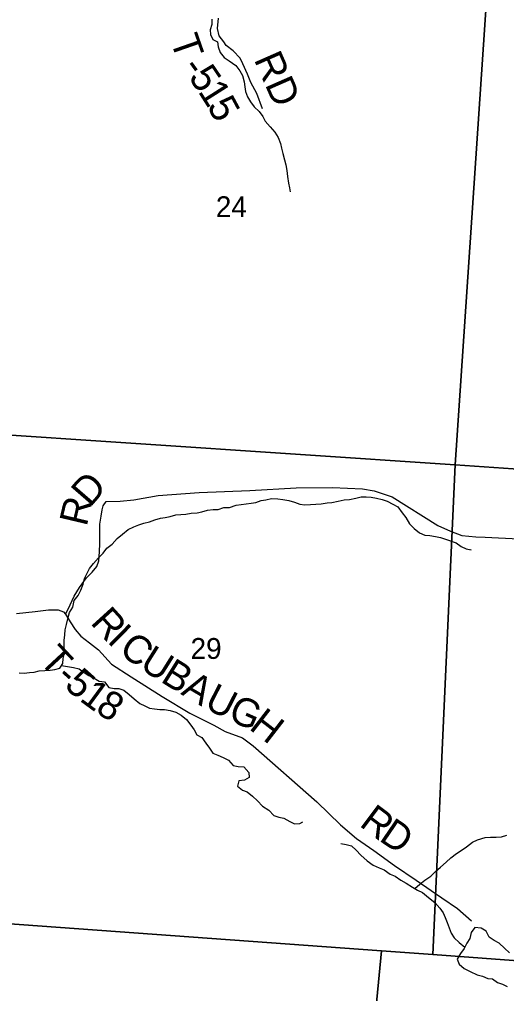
# Model space of a CAD drawing. Extents: x 1578669 to 1989827, y 208020 to 553079.
# Drawn here: x 1871261 to 1876425, y 410123 to 420455 of the extents above; entities that cross this region are included whole.
import ezdxf

# ---------------------------------------------------------------- set-up
doc = ezdxf.new("R2010")
doc.units = 0
for name, color, linetype in [('GM_X_County_Road', 7, 'Continuous'), ('GM_X_County_Road_Text', 7, 'Continuous'), ('GM_X_Minor_Lake', 7, 'Continuous'), ('GM_X_Minor_River', 7, 'Continuous'), ('GM_X_Section', 7, 'Continuous'), ('GM_X_Section_Text', 7, 'Continuous'), ('GM_X_Township_Road', 7, 'Continuous'), ('GM_X_Township_Road_Text', 7, 'Continuous')]:
    doc.layers.add(name, color=color, linetype=linetype)

msp = doc.modelspace()

# ---------------------------------------------------------------- linework, layer by layer
at = {"layer": 'GM_X_County_Road'}
for points in [[(1871750, 414147), (1871750, 414147), (1871776, 414199), (1871839, 414337), (1871896, 414431), (1871972, 414533), (1872032, 414592), (1872081, 414654), (1872101, 414714), (1872110, 414810), (1872112, 414897), (1872113, 414973), (1872113, 415101), (1872126, 415187), (1872136, 415255), (1872149, 415297), (1872181, 415343), (1872327, 415346), (1872473, 415359), (1872731, 415406), (1873165, 415438), (1873703, 415459), (1874196, 415488), (1874578, 415492), (1874897, 415476), (1875021, 415455), (1875211, 415392), (1875697, 415089), (1875829, 415028), (1875951, 414981), (1876098, 414966), (1876198, 414963), (1876554, 414947)], [(1871230, 414156), (1871426, 414177), (1871568, 414192), (1871670, 414192), (1871726, 414173), (1871750, 414147)]]:
    msp.add_lwpolyline(points, dxfattribs=at)
at = {"layer": 'GM_X_Minor_Lake'}
msp.add_lwpolyline([(1876457, 410555), (1876404, 410605), (1876347, 410656), (1876294, 410687), (1876241, 410720), (1876208, 410785), (1876155, 410816), (1876087, 410822), (1876050, 410769), (1876034, 410707), (1876005, 410656), (1875974, 410602), (1875935, 410547), (1875901, 410488), (1875924, 410433), (1875977, 410388), (1876038, 410356), (1876112, 410323), (1876171, 410307), (1876225, 410282), (1876277, 410279), (1876330, 410242), (1876381, 410221), (1876433, 410198)], dxfattribs=at)
at = {"layer": 'GM_X_Minor_River'}
for points in [[(1873299, 420459), (1873300, 420401), (1873283, 420347), (1873286, 420295), (1873311, 420244), (1873362, 420219), (1873369, 420165), (1873389, 420104), (1873430, 420053), (1873483, 420018), (1873556, 419966), (1873597, 419911), (1873624, 419861), (1873642, 419794), (1873651, 419740), (1873656, 419690), (1873677, 419635), (1873712, 419582), (1873750, 419529)], [(1873750, 419529), (1873801, 419480), (1873840, 419425), (1873865, 419375), (1873920, 419315), (1873968, 419260), (1874003, 419205), (1874028, 419141), (1874039, 419090), (1874053, 419032), (1874070, 418966), (1874085, 418913), (1874095, 418855), (1874104, 418791), (1874114, 418718), (1874125, 418668), (1874130, 418626)], [(1873768, 415331), (1873823, 415354), (1873873, 415361), (1873933, 415374), (1873999, 415372), (1874053, 415365), (1874115, 415354), (1874176, 415334), (1874232, 415315), (1874288, 415308), (1874348, 415310), (1874402, 415313), (1874460, 415318), (1874522, 415327), (1874572, 415331), (1874638, 415346), (1874705, 415359), (1874761, 415365), (1874827, 415378), (1874885, 415393), (1874937, 415393), (1874989, 415390), (1875047, 415377), (1875107, 415362), (1875158, 415347), (1875220, 415315), (1875273, 415286), (1875320, 415223), (1875358, 415172), (1875395, 415105), (1875446, 415056), (1875501, 415010), (1875560, 414987), (1875612, 414982), (1875672, 414971), (1875726, 414961), (1875777, 414944), (1875890, 414904), (1875945, 414864), (1875997, 414841), (1876051, 414830), (1876047, 414830)], [(1871258, 413524), (1871310, 413523), (1871366, 413528), (1871416, 413531), (1871471, 413546), (1871531, 413548), (1871585, 413555), (1871635, 413560), (1871687, 413573), (1871720, 413624), (1871725, 413678), (1871739, 413732), (1871736, 413802), (1871736, 413868), (1871741, 413928), (1871744, 413980), (1871760, 414038), (1871773, 414098), (1871790, 414164), (1871826, 414221), (1871841, 414291), (1871884, 414344), (1871910, 414401), (1871937, 414465), (1871952, 414524), (1871976, 414576), (1872005, 414633), (1872044, 414685), (1872097, 414746), (1872148, 414794), (1872186, 414848), (1872245, 414890), (1872298, 414949), (1872353, 414996), (1872412, 415045), (1872475, 415072), (1872525, 415096), (1872579, 415111), (1872640, 415128), (1872696, 415147), (1872755, 415167), (1872807, 415174), (1872857, 415185), (1872919, 415200), (1872973, 415203), (1873024, 415208), (1873080, 415220), (1873144, 415221), (1873196, 415234), (1873256, 415250), (1873313, 415257), (1873369, 415256), (1873429, 415279), (1873489, 415277), (1873558, 415304), (1873612, 415309), (1873666, 415316), (1873718, 415324), (1873768, 415331)], [(1871706, 413602), (1871770, 413593), (1871833, 413580), (1871893, 413566), (1871946, 413527), (1871997, 413498), (1872053, 413467), (1872104, 413438), (1872162, 413430), (1872207, 413371), (1872264, 413360), (1872316, 413359), (1872368, 413340), (1872423, 413294), (1872476, 413249), (1872537, 413198), (1872590, 413176), (1872641, 413149), (1872693, 413142), (1872749, 413135), (1872799, 413136), (1872859, 413126), (1872917, 413109), (1872974, 413076), (1873031, 413029), (1873079, 412971), (1873114, 412921), (1873143, 412868), (1873194, 412839), (1873235, 412778), (1873274, 412725), (1873311, 412672), (1873364, 412653), (1873422, 412627), (1873477, 412598), (1873526, 412543), (1873579, 412530), (1873639, 412528), (1873692, 412469), (1873697, 412415), (1873646, 412388), (1873586, 412381), (1873571, 412324), (1873624, 412280), (1873675, 412263), (1873732, 412218), (1873785, 412167), (1873838, 412109), (1873905, 412070), (1873958, 412013), (1874009, 411995), (1874063, 411984), (1874126, 411947), (1874178, 411924), (1874232, 411928), (1874266, 411946)], [(1875453, 411236), (1875507, 411285), (1875560, 411326), (1875621, 411369), (1875672, 411416), (1875725, 411465), (1875784, 411518), (1875835, 411561), (1875894, 411607), (1875945, 411640), (1876000, 411679), (1876065, 411730), (1876118, 411753), (1876200, 411777), (1876256, 411782), (1876316, 411782), (1876372, 411785), (1876427, 411802)], [(1874669, 411715), (1874725, 411705), (1874780, 411690), (1874831, 411645), (1874880, 411590), (1874947, 411532), (1875010, 411485), (1875075, 411455), (1875127, 411436), (1875190, 411391), (1875245, 411367), (1875304, 411326), (1875362, 411295), (1875429, 411251), (1875480, 411220), (1875533, 411195), (1875596, 411143), (1875665, 411088), (1875718, 411030), (1875754, 410980), (1875773, 410929), (1875794, 410877), (1875815, 410820), (1875838, 410765), (1875870, 410713), (1875923, 410663), (1875982, 410616)]]:
    msp.add_lwpolyline(points, dxfattribs=at)
at = {"layer": 'GM_X_Section'}
for points in [[(1871133, 421339), (1876234, 420979), (1875881, 415732), (1870798, 416070)], [(1876234, 420979), (1881581, 420807), (1881208, 415364), (1875881, 415732)], [(1870798, 416070), (1875881, 415732), (1875642, 410537), (1875100, 410575), (1870477, 410913)], [(1875881, 415732), (1881208, 415364), (1880920, 410149), (1880684, 410164), (1875642, 410537)], [(1869527, 410982), (1870477, 410913), (1875100, 410575), (1874599, 405341), (1869150, 405817)], [(1875100, 410575), (1875642, 410537), (1880684, 410164), (1880275, 404843), (1874599, 405341)]]:
    msp.add_lwpolyline(points, close=True, dxfattribs=at)
at = {"layer": 'GM_X_Township_Road'}
for points in [[(1873839, 419508), (1873776, 419669), (1873715, 419787), (1873678, 419876), (1873630, 419984), (1873601, 420046), (1873525, 420123), (1873453, 420181), (1873426, 420218), (1873378, 420282), (1873360, 420360), (1873371, 420471)], [(1871750, 414147), (1871799, 414065), (1871853, 413984), (1871910, 413914), (1872002, 413843), (1872098, 413770), (1872235, 413617), (1872444, 413482), (1872773, 413274), (1873066, 413098), (1873321, 412970), (1873440, 412903), (1873624, 412834), (1873738, 412751), (1874412, 412156), (1874665, 411912), (1874834, 411767), (1875019, 411642), (1875238, 411482), (1875467, 411326), (1875738, 411137), (1875905, 411025), (1876055, 410894)]]:
    msp.add_lwpolyline(points, dxfattribs=at)

# ---------------------------------------------------------------- texts
at = {"layer": 'GM_X_County_Road_Text'}
for s, rotation, p in [('D', 49.0652, (1872011, 415275)), ('R', 76.6804, (1871972, 415069))]:
    msp.add_text(s, height=300, rotation=rotation, dxfattribs=at).set_placement(p)
at = {"layer": 'GM_X_Section_Text'}
for s, p in [('24', (1873343, 418359)), ('29', (1873075, 413673))]:
    msp.add_text(s, height=221, rotation=0, dxfattribs=at).set_placement(p)
at = {"layer": 'GM_X_Township_Road_Text'}
for s, rotation, p in [('T', 289.1871, (1872857, 420238)), ('RD', 293.7139, (1873743, 420033)), ('-', 305.9646, (1872975, 419942)), ('5', 304.2212, (1873046, 419844)), ('1', 302.4025, (1873148, 419693)), ('5', 298.2292, (1873244, 419542)), ('R', 312.2585, (1872004, 414052)), ('I', 315.6177, (1872183, 413856)), ('C', 322.7381, (1872302, 413744)), ('T', 312.848, (1871459, 413647)), ('U', 327.9213, (1872522, 413577)), ('B', 327.9733, (1872746, 413437)), ('-', 318.0771, (1871633, 413461)), ('5', 318.2813, (1871725, 413378)), ('A', 329.5017, (1872963, 413302)), ('1', 323.6824, (1871887, 413236)), ('U', 332.9778, (1873208, 413158)), ('8', 327.4755, (1872054, 413114)), ('G', 336.1002, (1873459, 413031)), ('H', 322.2499, (1873684, 412934)), ('R', 323.141, (1874854, 411908)), ('D', 325.7259, (1875062, 411752))]:
    msp.add_text(s, height=300, rotation=rotation, dxfattribs=at).set_placement(p)

doc.saveas('drawing.dxf')
